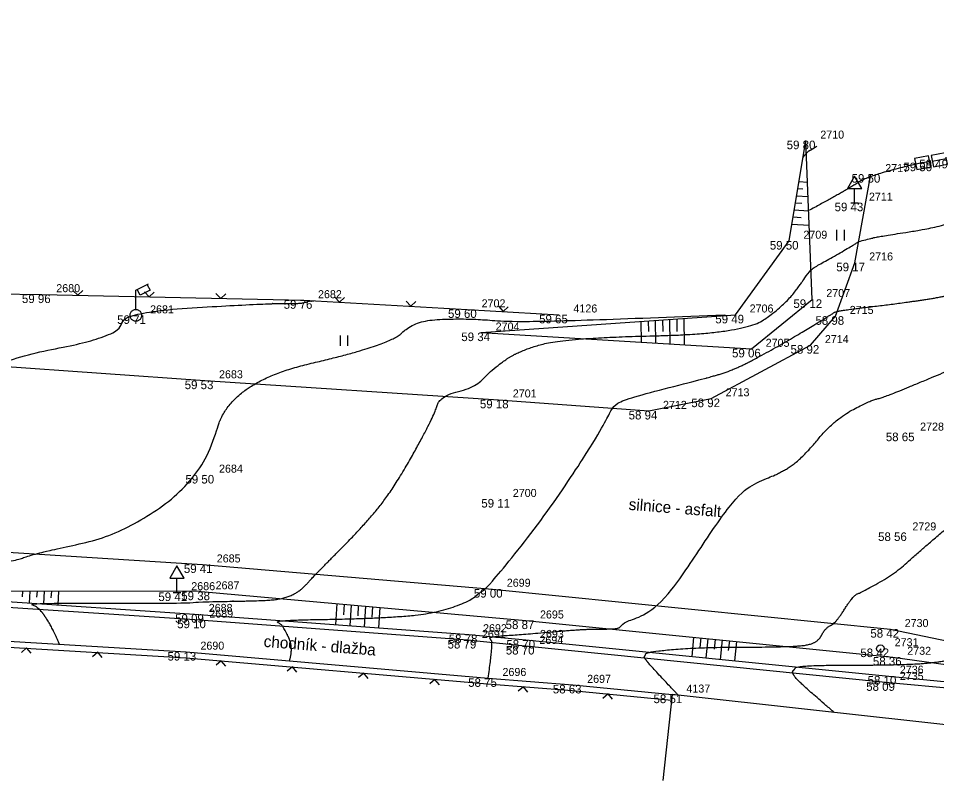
# Model space of a CAD drawing. Extents: x -704017 to -701500, y -1008977 to -1008450.
# Drawn here: x -702544.07 to -702511.97, y -1008774.48 to -1008747.83 of the extents above; entities that cross this region are included whole.
import ezdxf

# ---------------------------------------------------------------- set-up
doc = ezdxf.new("R2010")
doc.units = 0
for name, color, linetype in [('Z_body', 7, 'Continuous'), ('Z_body_cisla', 7, 'Continuous'), ('Z_body_vysky', 7, 'Continuous'), ('Z_budovy', 7, 'Continuous'), ('Z_chodnik', 7, 'Continuous'), ('Z_dopravni_znaceni', 7, 'Continuous'), ('Z_komunikace', 7, 'Continuous'), ('Z_oploceni', 7, 'Continuous'), ('Z_popis', 7, 'Continuous'), ('Z_rozhrani_ploch', 7, 'Continuous'), ('Z_site_znaky_kanalizace', 7, 'Continuous'), ('Z_site_znaky_VO', 7, 'Continuous'), ('Z_site_znaky_vodovod', 7, 'Continuous'), ('Z_teren_hrany_paty', 7, 'Continuous'), ('Z_vrstevnice_hlavni', 7, 'Continuous'), ('Z_vrstevnice_vedlejsi', 7, 'Continuous')]:
    doc.layers.add(name, color=color, linetype=linetype)

# ---------------------------------------------------------------- blocks, each defined once
blk = doc.blocks.new('POINT_DISPLAY')
blk.add_line((0, 0), (0, 0))
blk = doc.blocks.new('Z212')
for p, q in [((-0.17, 0.17), (0, 0)), ((0, 0), (0.17, 0.17))]:
    blk.add_line(p, q)
blk = doc.blocks.new('Z306')
for p, q in [((-0.13, 0.17), (-0.13, -0.2)), ((0.13, 0.17), (0.13, -0.2))]:
    blk.add_line(p, q)
blk = doc.blocks.new('Z13')
for p, q in [((0, 0.88), (0.45, 1.1)), ((0.4, 1.07), (0.5, 0.88)), ((0, 0.2), (0, 0.88)), ((0.15, 0.7), (0.05, 0.9)), ((0.5, 0.88), (0.15, 0.7)), ((-0.2, 0.05), (-0.15, 0.15)), ((-0.2, -0.05), (-0.2, 0.05)), ((-0.15, 0.15), (-0.05, 0.2)), ((-0.05, 0.2), (0.05, 0.2)), ((0.05, 0.2), (0.15, 0.15)), ((0.15, 0.15), (0.2, 0.05)), ((0.2, 0.05), (0.2, -0.05)), ((-0.15, -0.15), (-0.2, -0.05)), ((-0.05, -0.2), (-0.15, -0.15)), ((0.05, -0.2), (-0.05, -0.2)), ((0.15, -0.15), (0.05, -0.2)), ((0.2, -0.05), (0.15, -0.15))]:
    blk.add_line(p, q)
blk = doc.blocks.new('Z527')
for p, q in [((0, 0.93), (-0.25, 0.5)), ((0.25, 0.5), (0, 0.93)), ((-0.25, 0.5), (0.25, 0.5)), ((0, 0), (0, 0.5)), ((-0.13, 0), (0.13, 0))]:
    blk.add_line(p, q)
blk = doc.blocks.new('Z38')
for p, q in [((0.25, 0.2), (-0.25, 0.2)), ((-0.25, 0.2), (-0.25, -0.2)), ((-0.25, 0), (0.25, 0)), ((0.25, -0.2), (0.25, 0.2)), ((-0.25, -0.2), (0.25, -0.2))]:
    blk.add_line(p, q)
blk = doc.blocks.new('Z614')
for p, q in [((-0.13, 0.03), (-0.1, 0.08)), ((-0.13, -0.03), (-0.13, 0.03)), ((-0.1, 0.08), (-0.08, 0.1)), ((-0.08, 0.1), (-0.03, 0.13)), ((-0.03, 0.13), (0.03, 0.13)), ((0.03, 0.13), (0.08, 0.1)), ((0.08, 0.1), (0.1, 0.08)), ((0.1, 0.08), (0.13, 0.03)), ((0.13, 0.03), (0.13, -0.03)), ((-0.1, -0.08), (-0.13, -0.03)), ((-0.08, -0.1), (-0.1, -0.08)), ((-0.03, -0.13), (-0.08, -0.1)), ((0.03, -0.13), (-0.03, -0.13)), ((0.08, -0.1), (0.03, -0.13)), ((0.1, -0.08), (0.08, -0.1)), ((0.13, -0.03), (0.1, -0.08))]:
    blk.add_line(p, q)

msp = doc.modelspace()

# ---------------------------------------------------------------- linework, layer by layer
at = {"layer": 'Z_budovy'}
for p, q in [((-702521.22, -1008771.47), (-702521.55, -1008774.48)), ((-702511.19, -1008772.58), (-702521.22, -1008771.47))]:
    msp.add_line(p, q, dxfattribs=at)
at = {"layer": 'Z_chodnik'}
for p, q in [((-702549.78, -1008768.06), (-702537.9, -1008768.85)), ((-702537.9, -1008768.85), (-702528.37, -1008769.56)), ((-702528.37, -1008769.56), (-702526.36, -1008769.77)), ((-702526.36, -1008769.77), (-702513.76, -1008771.04)), ((-702513.76, -1008771.04), (-702506.68, -1008771.7))]:
    msp.add_line(p, q, dxfattribs=at)
at = {"layer": 'Z_komunikace'}
for p, q in [((-702514.83, -1008756.37), (-702514.27, -1008753.27)), ((-702515.51, -1008758.24), (-702514.83, -1008756.37)), ((-702516.38, -1008759.25), (-702515.51, -1008758.24)), ((-702519.85, -1008761.12), (-702516.38, -1008759.25)), ((-702547.82, -1008759.76), (-702537.56, -1008760.49)), ((-702537.56, -1008760.49), (-702527.29, -1008761.16)), ((-702527.29, -1008761.16), (-702522.04, -1008761.55)), ((-702522.04, -1008761.55), (-702519.85, -1008761.12)), ((-702548.83, -1008766.21), (-702537.64, -1008766.92)), ((-702537.64, -1008766.92), (-702527.5, -1008767.78)), ((-702527.5, -1008767.78), (-702513.59, -1008769.18)), ((-702513.59, -1008769.18), (-702509.28, -1008770.08))]:
    msp.add_line(p, q, dxfattribs=at)
at = {"layer": 'Z_oploceni'}
for p, q in [((-702546.57, -1008757.44), (-702543.25, -1008757.48)), ((-702543.25, -1008757.48), (-702534.1, -1008757.68)), ((-702534.1, -1008757.68), (-702528.38, -1008758)), ((-702528.38, -1008758), (-702525.17, -1008758.19)), ((-702550.02, -1008769.27), (-702538.21, -1008769.98)), ((-702550.03, -1008769.47), (-702538.22, -1008770.18)), ((-702538.22, -1008770.18), (-702527.67, -1008771.1)), ((-702538.21, -1008769.98), (-702527.65, -1008770.9)), ((-702527.67, -1008771.1), (-702524.71, -1008771.33)), ((-702527.65, -1008770.9), (-702524.69, -1008771.13)), ((-702524.69, -1008771.13), (-702521.22, -1008771.47)), ((-702524.71, -1008771.33), (-702521.24, -1008771.67))]:
    msp.add_line(p, q, dxfattribs=at)
at = {"layer": 'Z_rozhrani_ploch'}
for p, q in [((-702549.79, -1008767.85), (-702537.92, -1008768.66)), ((-702537.92, -1008768.66), (-702528.33, -1008769.37)), ((-702528.33, -1008769.37), (-702526.34, -1008769.56)), ((-702526.34, -1008769.56), (-702513.76, -1008770.82)), ((-702513.76, -1008770.82), (-702506.59, -1008771.51))]:
    msp.add_line(p, q, dxfattribs=at)
at = {"layer": 'Z_teren_hrany_paty'}
for p, q in [((-702517.13, -1008755.61), (-702516.54, -1008752.1)), ((-702516.33, -1008757.65), (-702516.54, -1008752.1)), ((-702516.78, -1008753.53), (-702516.49, -1008753.55)), ((-702516.82, -1008753.78), (-702516.65, -1008753.79)), ((-702516.86, -1008754.03), (-702516.47, -1008754.05)), ((-702516.91, -1008754.28), (-702516.68, -1008754.29)), ((-702516.99, -1008754.77), (-702516.71, -1008754.79)), ((-702516.95, -1008754.52), (-702516.45, -1008754.56)), ((-702517.03, -1008755.02), (-702516.43, -1008755.06)), ((-702519.01, -1008758.19), (-702517.13, -1008755.61)), ((-702518.45, -1008759.38), (-702516.33, -1008757.65)), ((-702527.89, -1008758.81), (-702519.01, -1008758.19)), ((-702521.31, -1008758.35), (-702521.3, -1008759.21)), ((-702521.06, -1008758.33), (-702521.05, -1008758.78)), ((-702520.81, -1008758.32), (-702520.8, -1008759.24)), ((-702522.31, -1008758.42), (-702522.3, -1008759.15)), ((-702522.06, -1008758.4), (-702522.05, -1008758.78)), ((-702521.81, -1008758.39), (-702521.8, -1008759.18)), ((-702521.56, -1008758.37), (-702521.55, -1008758.78)), ((-702527.89, -1008758.81), (-702518.45, -1008759.38)), ((-702537.68, -1008767.87), (-702549.79, -1008767.85)), ((-702543.93, -1008767.86), (-702543.94, -1008768.05)), ((-702543.67, -1008767.86), (-702543.7, -1008768.27)), ((-702543.42, -1008767.86), (-702543.44, -1008768.07)), ((-702543.17, -1008767.86), (-702543.2, -1008768.3)), ((-702542.92, -1008767.86), (-702542.94, -1008768.09)), ((-702542.67, -1008767.86), (-702542.7, -1008768.33)), ((-702537.68, -1008767.87), (-702526.34, -1008768.88)), ((-702532.94, -1008768.29), (-702532.99, -1008769.03)), ((-702532.69, -1008768.31), (-702532.71, -1008768.68)), ((-702532.44, -1008768.34), (-702532.49, -1008769.06)), ((-702532.19, -1008768.36), (-702532.21, -1008768.72)), ((-702531.94, -1008768.38), (-702531.99, -1008769.1)), ((-702531.69, -1008768.4), (-702531.72, -1008768.76)), ((-702531.44, -1008768.43), (-702531.49, -1008769.14)), ((-702526.34, -1008768.88), (-702513.5, -1008770.16)), ((-702520.47, -1008769.47), (-702520.53, -1008770.14)), ((-702520.22, -1008769.49), (-702520.25, -1008769.83)), ((-702519.97, -1008769.52), (-702520.04, -1008770.19)), ((-702519.72, -1008769.54), (-702519.75, -1008769.88)), ((-702519.47, -1008769.56), (-702519.54, -1008770.24)), ((-702519.22, -1008769.59), (-702519.26, -1008769.93)), ((-702518.97, -1008769.61), (-702519.04, -1008770.29)), ((-702513.5, -1008770.16), (-702509.2, -1008770.77))]:
    msp.add_line(p, q, dxfattribs=at)
at = {"layer": 'Z_vrstevnice_hlavni'}
msp.add_open_spline([(-702534.597, -1008770.295), (-702534.448, -1008769.819), (-702534.826, -1008769.079), (-702534.909, -1008769.013), (-702535.136, -1008768.866), (-702531.758, -1008768.82), (-702529.231, -1008768.623), (-702527.5, -1008767.78), (-702523.893, -1008762.637), (-702523.353, -1008761.453), (-702522.917, -1008761.139), (-702520.245, -1008760.465), (-702519.05, -1008760.126), (-702517.563, -1008759.324), (-702516.36, -1008758.61), (-702515.627, -1008758.156), (-702515.438, -1008758.043), (-702513.225, -1008757.789), (-702511.155, -1008757.467), (-702509.023, -1008756.634), (-702507.215, -1008755.859), (-702507.12, -1008756.013), (-702506.973, -1008756.243), (-702506.557, -1008756.728), (-702506.345, -1008756.967), (-702505.288, -1008756.628), (-702504.948, -1008756.552), (-702504.756, -1008756.512), (-702504.52, -1008756.504), (-702500.611, -1008755.707)], degree=2, dxfattribs=at)
at = {"layer": 'Z_vrstevnice_vedlejsi'}
for points in [[(-702591.383, -1008747.825), (-702590.503, -1008748.32), (-702589.635, -1008749.437), (-702589.352, -1008749.8), (-702588.838, -1008750.353), (-702587.312, -1008752.004), (-702586.328, -1008752.958), (-702585.68, -1008753.598), (-702585.12, -1008754.1), (-702584.887, -1008754.197), (-702584.278, -1008754.119), (-702583.643, -1008754.408), (-702582.575, -1008755.09), (-702581.96, -1008755.323), (-702582.298, -1008756.122), (-702581.19, -1008757.49), (-702579.27, -1008760.5), (-702576.041, -1008758.779), (-702569.201, -1008761.361), (-702568.264, -1008762.828), (-702562.973, -1008764.163), (-702556.89, -1008763.701), (-702549.17, -1008761.99), (-702548.2, -1008763.05), (-702545.621, -1008759.916), (-702540.471, -1008758.95), (-702540.495, -1008758.093), (-702535.274, -1008757.786), (-702534.25, -1008757.802), (-702533.983, -1008757.74), (-702533.952, -1008757.707), (-702533.743, -1008757.7)], [(-702516.638, -1008752.685), (-702516.525, -1008752.508), (-702516.31, -1008752.393), (-702516.162, -1008752.295)], [(-702512.46, -1008752.87), (-702514.27, -1008753.27), (-702515.162, -1008753.859), (-702516.447, -1008754.549)], [(-702542.639, -1008769.714), (-702542.838, -1008769.212), (-702543.3, -1008768.491), (-702543.501, -1008768.378), (-702543.675, -1008768.267), (-702538.225, -1008768.28), (-702537.788, -1008768.224), (-702535.654, -1008768.195), (-702534.789, -1008768.127), (-702534.197, -1008767.839), (-702533.683, -1008767.256), (-702532.12, -1008765.699), (-702530.977, -1008764.328), (-702529.537, -1008761.735), (-702529.344, -1008761.026), (-702528.112, -1008760.74), (-702527.553, -1008760.132), (-702526.574, -1008759.427), (-702524.856, -1008758.993), (-702518.697, -1008758.854), (-702517.272, -1008757.84), (-702516.604, -1008756.952), (-702516.37, -1008756.589), (-702515.705, -1008756.233), (-702514.833, -1008755.724), (-702514.694, -1008755.618), (-702514.255, -1008755.522), (-702514.093, -1008755.47), (-702511.525, -1008755.071), (-702508.88, -1008754.038), (-702508.745, -1008753.995), (-702508.587, -1008753.97), (-702508.468, -1008753.928), (-702508.329, -1008753.854), (-702508.071, -1008753.863), (-702507.8, -1008754.437), (-702507.62, -1008754.728), (-702507.494, -1008754.926), (-702506.879, -1008754.827), (-702506, -1008754.776), (-702505.231, -1008754.636), (-702504.301, -1008754.446), (-702502.103, -1008754.372), (-702501.156, -1008754.179)], [(-702527.65, -1008770.9), (-702527.477, -1008769.653), (-702527.591, -1008769.52), (-702527.584, -1008769.441), (-702526.34, -1008769.36), (-702524.379, -1008769.182), (-702523.319, -1008769.181), (-702523.033, -1008769.141), (-702522.94, -1008768.96), (-702521.504, -1008768.383), (-702518.953, -1008764.338), (-702517.722, -1008763.86), (-702516.766, -1008763.33), (-702515.569, -1008761.869), (-702514.283, -1008761.177), (-702513.795, -1008761.077), (-702510.968, -1008759.888), (-702510.864, -1008759.877), (-702510.785, -1008759.864), (-702510.703, -1008759.832), (-702510.591, -1008759.784), (-702505.853, -1008757.953), (-702505.749, -1008758.075), (-702505.58, -1008758.265), (-702505.098, -1008758.697), (-702504.876, -1008758.883), (-702504.005, -1008758.519), (-702503.482, -1008758.333), (-702502.394, -1008758.065), (-702500.844, -1008757.777), (-702499.343, -1008757.118)], [(-702554.503, -1008768.976), (-702557.93, -1008767.676), (-702558.126, -1008767.776), (-702558.19, -1008767.663), (-702558.952, -1008767.326), (-702558.96, -1008767.166), (-702558.97, -1008767.124), (-702558.163, -1008767.114), (-702557.665, -1008767.13), (-702556.581, -1008767.139), (-702552.777, -1008767.151), (-702549.31, -1008767.03), (-702544.37, -1008766.874), (-702543.564, -1008766.544), (-702540.435, -1008765.896), (-702537.56, -1008763.79), (-702536.68, -1008760.547), (-702531.047, -1008759.24), (-702530.256, -1008758.38), (-702528.192, -1008758.312), (-702526.486, -1008758.49), (-702519.395, -1008758.19)], [(-702521.002, -1008771.494), (-702521.042, -1008771.46), (-702522.229, -1008770.186), (-702522.16, -1008770.12), (-702522.147, -1008769.98), (-702520.295, -1008769.812), (-702517.025, -1008769.809), (-702516.144, -1008769.686), (-702515.857, -1008769.127), (-702515.509, -1008768.987), (-702514.89, -1008768.006), (-702514.592, -1008767.89), (-702513.436, -1008767.249), (-702512.578, -1008766.462), (-702510.5, -1008764.7), (-702509.235, -1008763.065), (-702508.298, -1008762.872), (-702507.222, -1008762.42), (-702504.01, -1008760.05), (-702502.592, -1008761.081), (-702502.082, -1008760.79), (-702501.174, -1008760.378), (-702499.613, -1008759.927), (-702499.089, -1008759.845), (-702498.071, -1008759.493), (-702497.733, -1008759.375), (-702496.916, -1008759.016)], [(-702515.551, -1008772.097), (-702516.602, -1008771.204), (-702517.065, -1008770.707), (-702516.91, -1008770.558), (-702516.905, -1008770.505), (-702516.211, -1008770.442), (-702513.61, -1008770.439), (-702512.022, -1008770.37), (-702510.921, -1008770.111), (-702510.537, -1008769.818), (-702509.698, -1008769.413), (-702509.487, -1008769.219), (-702509.091, -1008768.884), (-702506.45, -1008766.935), (-702505.364, -1008766.536), (-702501.609, -1008762.469), (-702501.239, -1008762.181), (-702501.08, -1008762.265), (-702500.959, -1008762.33), (-702499.768, -1008762.768), (-702499.238, -1008762.582), (-702498.842, -1008762.527), (-702497.03, -1008762.51), (-702496.307, -1008762.053), (-702495.426, -1008761.674), (-702495.384, -1008761.634), (-702493.232, -1008761.347)]]:
    msp.add_open_spline(points, degree=2, dxfattribs=at)

# ---------------------------------------------------------------- block references
at = {"layer": 'Z_body'}
for p in [(-702516.54, -1008752.1), (-702512.46, -1008752.87), (-702514.27, -1008753.27), (-702514.84, -1008754.27), (-702517.13, -1008755.61), (-702514.83, -1008756.37), (-702543.25, -1008757.48), (-702534.1, -1008757.68), (-702516.33, -1008757.65), (-702528.38, -1008758), (-702539.97, -1008758.21), (-702525.17, -1008758.19), (-702519.01, -1008758.19), (-702515.51, -1008758.24), (-702527.89, -1008758.81), (-702516.38, -1008759.25), (-702518.45, -1008759.38), (-702537.56, -1008760.49), (-702527.29, -1008761.16), (-702519.85, -1008761.12), (-702522.04, -1008761.55), (-702513.05, -1008762.31), (-702537.56, -1008763.79), (-702527.29, -1008764.63), (-702513.32, -1008765.8), (-702537.64, -1008766.92), (-702538.53, -1008767.9), (-702537.68, -1008767.87), (-702527.5, -1008767.78), (-702537.92, -1008768.66), (-702537.9, -1008768.85), (-702526.34, -1008768.88), (-702513.59, -1008769.18), (-702528.37, -1008769.56), (-702528.33, -1008769.37), (-702526.34, -1008769.56), (-702526.36, -1008769.77), (-702513.94, -1008769.86), (-702538.21, -1008769.98), (-702513.5, -1008770.16), (-702513.76, -1008770.82), (-702527.65, -1008770.9), (-702524.69, -1008771.13), (-702513.76, -1008771.04), (-702521.22, -1008771.47)]:
    msp.add_blockref('POINT_DISPLAY', p, dxfattribs=at)
at = {"layer": 'Z_dopravni_znaceni'}
for p in [(-702514.84, -1008754.27), (-702538.53, -1008767.9)]:
    msp.add_blockref('Z527', p, dxfattribs=at)
at = {"layer": 'Z_oploceni'}
for p, rotation in [((-702542, -1008757.51), -1.3000000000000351), ((-702539.5, -1008757.56), -1.3000000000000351), ((-702537, -1008757.62), -1.3000000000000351), ((-702532.85, -1008757.75), -3.2000000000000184), ((-702530.36, -1008757.89), -3.2000000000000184), ((-702527.13, -1008758.07), -3.400000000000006), ((-702543.79, -1008769.84), 176.6), ((-702541.3, -1008769.99), 176.6), ((-702536.98, -1008770.29), 175), ((-702534.49, -1008770.5), 175), ((-702532, -1008770.72), 175), ((-702529.51, -1008770.94), 175), ((-702526.42, -1008771.2), 175.6), ((-702523.46, -1008771.45), 174.4)]:
    msp.add_blockref('Z212', p, dxfattribs=dict(at, rotation=rotation))
at = {"layer": 'Z_popis'}
for p in [(-702515.34, -1008755.39), (-702532.7, -1008759.08)]:
    msp.add_blockref('Z306', p, dxfattribs=at)
at = {"layer": 'Z_site_znaky_kanalizace', "rotation": 10.799999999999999}
for p in [(-702511.88, -1008752.77), (-702512.46, -1008752.87)]:
    msp.add_blockref('Z38', p, dxfattribs=at)
at = {"layer": 'Z_site_znaky_VO'}
msp.add_blockref('Z13', (-702539.97, -1008758.21), dxfattribs=at)
at = {"layer": 'Z_site_znaky_vodovod', "rotation": 10.799999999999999}
msp.add_blockref('Z614', (-702513.94, -1008769.86), dxfattribs=at)

# ---------------------------------------------------------------- texts
at = {"layer": 'Z_body_cisla'}
for s, p in [('2710', (-702516.04, -1008752.03)), ('2717', (-702513.77, -1008753.2)), ('2711', (-702514.34, -1008754.2)), ('2709', (-702516.63, -1008755.53)), ('2716', (-702514.33, -1008756.29)), ('2680', (-702542.75, -1008757.4)), ('2682', (-702533.6, -1008757.61)), ('2707', (-702515.83, -1008757.57)), ('2702', (-702527.88, -1008757.93)), ('2681', (-702539.47, -1008758.14)), ('4126', (-702524.67, -1008758.11)), ('2706', (-702518.51, -1008758.11)), ('2715', (-702515.01, -1008758.16)), ('2704', (-702527.39, -1008758.74)), ('2714', (-702515.88, -1008759.18)), ('2705', (-702517.95, -1008759.31)), ('2683', (-702537.06, -1008760.41)), ('2701', (-702526.79, -1008761.08)), ('2713', (-702519.35, -1008761.04)), ('2712', (-702521.54, -1008761.48)), ('2728', (-702512.55, -1008762.24)), ('2684', (-702537.06, -1008763.71)), ('2700', (-702526.79, -1008764.56)), ('2729', (-702512.82, -1008765.73)), ('2685', (-702537.14, -1008766.85)), ('2686', (-702538.03, -1008767.82)), ('2687', (-702537.18, -1008767.79)), ('2699', (-702527, -1008767.7)), ('2688', (-702537.42, -1008768.58)), ('2689', (-702537.4, -1008768.78)), ('2695', (-702525.84, -1008768.81)), ('2730', (-702513.09, -1008769.11)), ('2691', (-702527.87, -1008769.49)), ('2692', (-702527.83, -1008769.29)), ('2693', (-702525.84, -1008769.49)), ('2694', (-702525.86, -1008769.7)), ('2731', (-702513.44, -1008769.78)), ('2690', (-702537.71, -1008769.9)), ('2732', (-702513, -1008770.08)), ('2696', (-702527.15, -1008770.82)), ('2736', (-702513.26, -1008770.74)), ('2697', (-702524.19, -1008771.06)), ('2735', (-702513.26, -1008770.96)), ('4137', (-702520.72, -1008771.4))]:
    msp.add_text(s, height=0.28, dxfattribs=at).set_placement(p)
at = {"layer": 'Z_body_vysky'}
for s, p in [('59 80', (-702517.215, -1008752.4)), ('59 50', (-702513.135, -1008753.17)), ('59 49', (-702512.58, -1008753.07)), ('59 50', (-702514.945, -1008753.57)), ('59 43', (-702515.54, -1008754.57)), ('59 50', (-702517.805, -1008755.91)), ('59 17', (-702515.48, -1008756.67)), ('59 96', (-702543.95, -1008757.78)), ('59 76', (-702534.8, -1008757.98)), ('59 12', (-702516.98, -1008757.95)), ('59 60', (-702529.055, -1008758.3)), ('59 71', (-702540.62, -1008758.51)), ('59 65', (-702525.87, -1008758.49)), ('59 49', (-702519.71, -1008758.49)), ('58 98', (-702516.21, -1008758.54)), ('59 34', (-702528.59, -1008759.11)), ('58 92', (-702517.08, -1008759.55)), ('59 06', (-702519.125, -1008759.68)), ('59 53', (-702538.26, -1008760.79)), ('59 18', (-702527.94, -1008761.46)), ('58 92', (-702520.55, -1008761.42)), ('58 94', (-702522.74, -1008761.85)), ('58 65', (-702513.75, -1008762.61)), ('59 50', (-702538.235, -1008764.09)), ('59 11', (-702527.89, -1008764.93)), ('58 56', (-702514.02, -1008766.1)), ('59 41', (-702538.29, -1008767.22)), ('59 41', (-702539.18, -1008768.2)), ('59 38', (-702538.38, -1008768.17)), ('59 00', (-702528.15, -1008768.08)), ('59 09', (-702538.595, -1008768.96)), ('59 10', (-702538.525, -1008769.15)), ('58 87', (-702527.04, -1008769.18)), ('58 42', (-702514.29, -1008769.48)), ('58 79', (-702529.07, -1008769.86)), ('58 78', (-702529.03, -1008769.67)), ('58 70', (-702527.015, -1008769.86)), ('58 70', (-702527.035, -1008770.07)), ('58 42', (-702514.64, -1008770.16)), ('59 13', (-702538.86, -1008770.28)), ('58 36', (-702514.2, -1008770.46)), ('58 10', (-702514.385, -1008771.12)), ('58 75', (-702528.35, -1008771.2)), ('58 63', (-702525.39, -1008771.43)), ('58 09', (-702514.435, -1008771.34)), ('58 51', (-702521.87, -1008771.77))]:
    msp.add_text(s, height=0.3, dxfattribs=at).set_placement(p)
at = {"layer": 'Z_popis'}
for s, p in [('silnice - asfalt', (-702522.75, -1008765.01)), ('chodník - dlažba', (-702535.51, -1008769.8))]:
    msp.add_text(s, height=0.4, rotation=355.5, dxfattribs=at).set_placement(p)

doc.saveas('drawing.dxf')
